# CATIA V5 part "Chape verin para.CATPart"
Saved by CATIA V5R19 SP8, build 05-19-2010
Part number: Chape verin para
Bounding box of the stored display mesh (mm): x -125 to 125, y 410 to 530, z -445 to -360
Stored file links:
  G:\EU_thinkMotion\CFAO_2010\MMS_groupe3\MMS_groupe3\rdalborgo\rdalborgo\Chape verin para.CATPart
  G:\EU_thinkMotion\CFAO_2010\MMS_groupe3\MMS_groupe3\rdalborgo\rdalborgo\rdalborgo.CATProduct
  G:\EU_thinkMotion\CFAO_2010\MMS_groupe3\MMS_groupe3\rdalborgo\rdalborgo\Bielle M.CATPart
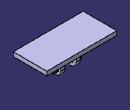
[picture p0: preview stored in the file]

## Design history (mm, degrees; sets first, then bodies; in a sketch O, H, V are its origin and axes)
External parameters (linked from other documents)
  `External.Largeur bielle` = 210 mm
Set1
  Plane1: linked copy from another document
  Plane2: linked copy from another document
  Point1: linked copy from another document
  Point2 "A verin para": linked copy from another document
  Plane3: linked copy from another document
Body1 (main body)
  Sketch1 on Plane2, origin (0, 470, 0), H (-1, 0, 0), V (0, 0, 1)
    line L1 (-125, -360) -> (125, -360)
    line L2 (125, -360) -> (125, -375)
    line L3 (125, -375) -> (35, -375)
    line L4 (35, -375) -> (35, -445)
    line L5 (35, -445) -> (20, -445)
    line L6 (20, -445) -> (20, -375)
    line L7 (20, -375) -> (-20, -375)
    line L8 (-20, -375) -> (-20, -445)
    point P9 (-20, -445)
    line L9 (-20, -445) -> (-35, -445)
    line L10 (-35, -445) -> (-35, -375)
    point P11 (-35, -375)
    line L11 (-35, -375) -> (-125, -375)
    line L12 (-125, -375) -> (-125, -360)
    reference intersected line E1 through (0, -360) direction (-1, 0) from Plane1
    reference projected point E2 (0, -360) from Point1
    reference projected point E3 (0, -360) from Point1
    reference projected point E4 (0, -425) from Point2
    length L1 = 250 {= `External.Largeur bielle` +40mm}
    distance L11 L1 = 15
    distance L8 L10 = 15
    distance L4 L6 = 15
    distance L2 E2 = 125 {= (`External.Largeur bielle` +40mm)/2}
    distance L8 L6 = 40
    distance L10 E3 = 35
    distance L9 E4 = 20
    horizontal: L1 H, L3 H, L5 H, L7 H, L9 H, L11 H
    vertical: L2 V, L4 V, L6 V, L8 V, L10 V, L12 V
    coincidence: P9 L5, P11 L7, L7 L3, L9 L5, L1 E1
  Sketch2 on Plane3, origin (0, 0, 0), H (0, 1, 0), V (0, 0, 1)
    line L1 (410, -360) -> (530, -360)
    line L2 (530, -360) -> (530, -375)
    line L3 (530, -375) -> (490, -375)
    line L4 (490, -375) -> (490, -425)
    point P5 (490, -425)
    line L5 (450, -425) -> (450, -375)
    point P7 (450, -375)
    line L6 (450, -375) -> (410, -375)
    line L7 (410, -375) -> (410, -360)
    reference intersected line E1 through (0, -360) direction (-1, 0) from Plane1
    point P9 (470, -425)
    arc A1 centre (470, -425) radius 20 from (450, -425) to (490, -425) ccw
    point P10 (490, -425)
    reference projected point E2 (470, -425) from Point2
    reference projected point E3 (470, -360) from Point1
    distance L1 L3 = 15
    distance L2 L7 = 120
    distance L5 L4 = 40
    distance L7 L5 = 40
    radius A1 = 20
    distance L2 E3 = 60
    horizontal: L1 H, L3 H, L6 H
    vertical: L2 V, L4 V, L5 V, L7 V
    coincidence: P7 L3, L1 E1, P9 E2, P5 P10
  SolidCombine1: FirstComponentProfile Sketch2, FirstComponentDirection Sketch2, SecondComponentProfile Sketch1, SecondComponentDirection Sketch1
  Sketch3 on face of SolidCombine1 from Sketch1.L10, origin (35, 0, 0), H (0, 1, 0), V (0, 0, 1)
    circle A1 centre (470, -425) radius 10
    point P1 (470, -425)
    reference projected point E1 (470, -425) from Point2
    radius A1 = 10
    coincidence: P1 E1
  Pocket1: profile Sketch3, direction (-1, 0, 0), through (limit type 3)
Body2 "Axe Verin"
  Sketch4 on Plane3, origin (0, 0, 0), H (0, 1, 0), V (0, 0, 1)
    circle A1 centre (470, -425) radius 10
    point P1 (470, -425)
    reference projected point E1 (470, -425) from Point2
    radius A1 = 10
    coincidence: E1 P1
  Pad1: profile Sketch4, direction (1, 0, 0), length 35, mirrored extent
  Sketch5 on start face of Pad1, origin (-35, 0, 0), H (0, -1, 0), V (0, 0, 1)
    circle A1 centre (-470, -425) radius 15
    point P1 (-470, -425)
    reference projected point E1 (-470, -425) from Point2
    radius A1 = 15
    coincidence: P1 E1
  Pad2: profile Sketch5, direction (-1, 0, 0), length 5
  Sketch6 on end face of Pad2, origin (-40, 0, 0), H (0, -1, 0), V (0, 0, 1)
    point P1 (-470, -425)
    point P2 (-466.7126, -437.2689)
    point P3 (-457.7311, -428.2874)
    point P4 (-461.0185, -416.0185)
    point P5 (-473.2874, -412.7311)
    point P6 (-482.2689, -421.7126)
    point P7 (-478.9815, -433.9815)
    point P8 (-462.2218, -432.7782)
    line L1 (-466.7126, -437.2689) -> (-457.7311, -428.2874)
    line L2 (-457.7311, -428.2874) -> (-461.0185, -416.0185)
    line L3 (-461.0185, -416.0185) -> (-473.2874, -412.7311)
    line L4 (-473.2874, -412.7311) -> (-482.2689, -421.7126)
    line L5 (-482.2689, -421.7126) -> (-478.9815, -433.9815)
    line L6 (-478.9815, -433.9815) -> (-466.7126, -437.2689)
    construction line L7 (-470, -425) -> (-462.2218, -432.7782)
    construction circle A1 centre (-470, -425) radius 12.7017
    construction arc A2 centre (-482.2689, -421.7126) radius 12.7017 from (-473.2874, -412.7311) to (-478.9815, -433.9815) cw
    construction arc A3 centre (-457.7311, -428.2874) radius 12.7017 from (-461.0185, -416.0185) to (-466.7126, -437.2689) ccw
    reference projected point E1 (-470, -425) from Point2
    distance L3 L6 = 22
    coincidence: A1 P2, A1 P3, A1 P4, A1 P5, A1 P6, A1 P7, A2 P1, A3 P1, P1 E1
    midpoint: P8 L1
    parallelism: L1 L4
  Pad3: profile Sketch6, direction (-1, 0, 0), length 8
  Sketch7 on end face of Pad1, origin (35, 0, 0), H (0, 1, 0), V (0, 0, 1)
    circle A1 centre (470, -425) radius 7.5
    point P1 (470, -425)
    reference projected point E1 (470, -425) from Point2
    radius A1 = 7.5
    coincidence: P1 E1
  Pad4: profile Sketch7, direction (1, 0, 0), length 12
  Sketch8 on end face of Pad1, origin (35, 0, 0), H (0, 1, 0), V (0, 0, 1)
    circle A1 centre (470, -425) radius 12.5
    point P1 (470, -425)
    circle A2 centre (470, -425) radius 7.5
    reference projected point E1 (470, -425) from Point2
    radius A1 = 12.5
    radius A2 = 7.5
    coincidence: P1 E1
  Pad5: profile Sketch8, direction (1, 0, 0), length 3
  Sketch9 on end face of Pad5, origin (38, 0, 0), H (0, 1, 0), V (0, 0, 1)
    point P1 (470, -425)
    point P2 (475.0896, -414.6352)
    point P3 (463.5686, -415.4099)
    point P4 (458.479, -425.7747)
    point P5 (464.9104, -435.3648)
    point P6 (476.4314, -434.5901)
    point P7 (481.521, -424.2253)
    point P8 (469.3291, -415.0225)
    line L1 (475.0896, -414.6352) -> (463.5686, -415.4099)
    line L2 (463.5686, -415.4099) -> (458.479, -425.7747)
    line L3 (458.479, -425.7747) -> (464.9104, -435.3648)
    line L4 (464.9104, -435.3648) -> (476.4314, -434.5901)
    line L5 (476.4314, -434.5901) -> (481.521, -424.2253)
    line L6 (481.521, -424.2253) -> (475.0896, -414.6352)
    construction line L7 (470, -425) -> (469.3291, -415.0225)
    construction circle A1 centre (470, -425) radius 11.547
    construction arc A2 centre (476.4314, -434.5901) radius 11.547 from (464.9104, -435.3648) to (481.521, -424.2253) cw
    construction arc A3 centre (463.5686, -415.4099) radius 11.547 from (458.479, -425.7747) to (475.0896, -414.6352) ccw
    reference projected point E1 (470, -425) from Point2
    circle A4 centre (470, -425) radius 7.5
    point P9 (470, -425)
    reference projected point E2 (470, -425) from Point2
    distance L1 L4 = 20
    radius A4 = 7.5
    coincidence: A1 P2, A1 P3, A1 P4, A1 P5, A1 P6, A1 P7, A2 P1, A3 P1, P1 E1, P9 E2
    midpoint: P8 L1
  Pad6: profile Sketch9, direction (1, 0, 0), length 8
